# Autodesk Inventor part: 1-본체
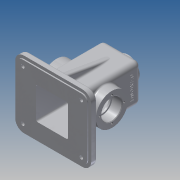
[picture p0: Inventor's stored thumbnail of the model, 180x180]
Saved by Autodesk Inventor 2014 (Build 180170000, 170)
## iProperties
Created: 2015-12
Part Number: 1-본체
Material: 알루미늄 6061
Document SubType Name: Modeling
Designer: Administrator
Mass: 888.312 g
Surface Area: 957.344 cm^2
Volume: 327.79 cm^3
Density: 2.71 g/cm^3
Appearance: 알루미늄 - 평지
Author: Administrator
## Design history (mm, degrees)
sketch "스케치1"
  geometry: L1 (-50, 57.5)-(50, 57.5); L2 (65, 42.5)-(65, -42.5); L3 (50, -57.5)-(-50, -57.5); L4 (-65, -42.5)-(-65, 42.5); L5 (-65, 57.5)-(65, -57.5); L6 (65, 57.5)-(-65, -57.5); A1 r 15 centre (50, -42.5) between (50, -57.5) and (65, -42.5); A2 r 15 centre (-50, -42.5) between (-65, -42.5) and (-50, -57.5); A3 r 15 centre (-50, 42.5) between (-50, 57.5) and (-65, 42.5); A4 r 15 centre (50, 42.5) between (65, 42.5) and (50, 57.5); 1 further point
  constraints: 12 end point, 8 point on circle, 8 point on line, 8 tangent, 4 centre point, 3 equal radius, 2 midpoint, 2 parallel, 1 horizontal, 1 perpendicular
  dimensions: "d0" = 130 distance of L5.end L6.end; "d1" = 115 distance of L6.start L5.end; "d4" = 15 radius of A1
extrude "돌출1" new body sketch "스케치1" distance "d2" = 10; taper "d3" = 0 deg
sketch "스케치2"
  geometry: L1 (-24.5, 32.5)-(24.5, 32.5); L2 (32.5, 24.5)-(32.5, -24.5); L3 (24.5, -32.5)-(-24.5, -32.5); L4 (-32.5, -24.5)-(-32.5, 24.5); L5 (-32.5, 32.5)-(32.5, -32.5); L6 (32.5, 32.5)-(-32.5, -32.5); A1 r 8 centre (-24.5, 24.5) between (-24.5, 32.5) and (-32.5, 24.5); A2 r 8 centre (24.5, 24.5) between (32.5, 24.5) and (24.5, 32.5); A3 r 8 centre (24.5, -24.5) between (24.5, -32.5) and (32.5, -24.5); A4 r 8 centre (-24.5, -24.5) between (-32.5, -24.5) and (-24.5, -32.5); 1 further point
  constraints: 12 end point, 8 point on circle, 8 point on line, 8 tangent, 4 centre point, 3 equal radius, 2 midpoint, 2 parallel, 1 horizontal, 1 perpendicular
  dimensions: "d5" = 65 distance of L5.end L6.end; "d6" = 65 distance of L6.start L5.end; "d7" = 8 radius of A1
extrude "돌출2" join sketch "스케치2" distance "d8" = 108; taper "d9" = 0 deg
sketch "스케치3"
  geometry: L1 (-65, -42.5)-(-65, 42.5) reference; L2 (50, -57.5)-(-50, -57.5) reference; L3 (65, 42.5)-(65, -42.5) reference; L4 (-50, 57.5)-(50, 57.5) reference; L5 (60, 42.5)-(60, -42.5); L6 (50, -52.5)-(-50, -52.5); L7 (-60, -42.5)-(-60, 42.5); L8 (-50, 52.5)-(50, 52.5); A1 r 15 centre (-50, -42.5) between (-65, -42.5) and (-50, -57.5) reference; A2 r 15 centre (50, -42.5) between (50, -57.5) and (65, -42.5) reference; A3 r 15 centre (50, 42.5) between (65, 42.5) and (50, 57.5) reference; A4 r 15 centre (-50, 42.5) between (-50, 57.5) and (-65, 42.5) reference; A5 r 10 centre (50, 42.5) between (60, 42.5) and (50, 52.5); A6 r 10 centre (50, -42.5) between (50, -52.5) and (60, -42.5); A7 r 10 centre (-50, -42.5) between (-60, -42.5) and (-50, -52.5); A8 r 10 centre (-50, 42.5) between (-50, 52.5) and (-60, 42.5); 1 further point
  constraints: 8 end point, 8 point on circle, 4 centre point, 7 other
  dimensions: "d10" = 5 distance between parallel lines of L4 L8
extrude "돌출3" join sketch "스케치3" distance "d11" = 2; taper "d12" = 0 deg
sketch "스케치4"
  geometry: L1 (-18, 0)-(67, 0) reference; L2 (67, -12)-(-18, -12) reference; C1 r 27.5 at (24.5, 43); 2 further points
  constraints: 1 centre point, 1 midpoint, 1 vertical alignment
  dimensions: "d13" = 55 diameter of C1; "d14" = 55 distance from line of L2 C1.centre
extrude "돌출4" join sketch "스케치4" distance "d15" = 15; taper "d16" = 0 deg
feature "쉘1" dims "d17" = 5
sketch "스케치5"
  geometry: L1 (22.5, -23)-(22.5, -72) reference; L2 (74.5, -20)-(25.5, -20) reference; L3 (77.5, -72)-(77.5, -23) reference; L4 (25.5, -75)-(74.5, -75) reference; L5 (105, -5)-(105, -90) reference; L6 (-5, -90)-(-5, -5) reference; L7 (100, -95)-(0, -95) reference; L8 (0, 0)-(100, 0) reference; L9 (22.5, -23)-(22.5, -72) reference; L10 (74.5, -20)-(25.5, -20) reference; L11 (77.5, -72)-(77.5, -23) reference; L12 (25.5, -75)-(74.5, -75) reference; L13 (105, -5)-(105, -90) reference; L14 (0, 0)-(100, 0) reference; L15 (-5, -90)-(-5, -5) reference; L16 (100, -95)-(0, -95) reference; A1 r 3 centre (25.5, -72) between (22.5, -72) and (25.5, -75) reference; A2 r 3 centre (25.5, -23) between (25.5, -20) and (22.5, -23) reference; A3 r 3 centre (74.5, -23) between (77.5, -23) and (74.5, -20) reference; A4 r 3 centre (74.5, -72) between (74.5, -75) and (77.5, -72) reference; A5 r 5 centre (100, -5) between (105, -5) and (100, 0) reference; A6 r 5 centre (0, -5) between (0, 0) and (-5, -5) reference; A7 r 5 centre (0, -90) between (-5, -90) and (0, -95) reference; A8 r 5 centre (100, -90) between (100, -95) and (105, -90) reference; A9 r 3 centre (25.5, -72) between (22.5, -72) and (25.5, -75) reference; A10 r 3 centre (25.5, -23) between (25.5, -20) and (22.5, -23) reference; A11 r 3 centre (74.5, -23) between (77.5, -23) and (74.5, -20) reference; A12 r 3 centre (74.5, -72) between (74.5, -75) and (77.5, -72) reference; A13 r 5 centre (100, -5) between (105, -5) and (100, 0) reference; A14 r 5 centre (0, -5) between (0, 0) and (-5, -5) reference; A15 r 5 centre (0, -90) between (-5, -90) and (0, -95) reference; A16 r 5 centre (100, -90) between (100, -95) and (105, -90) reference; 1 further point
extrude "돌출5" join sketch "스케치5" stored distance "d18" = 15; taper "d19" = 0 deg
sketch "스케치6"
  geometry: C1 r 20 at (0, 0); 1 further point
  constraints: 1 centre point, 1 coincident
  dimensions: "d20" = 40 diameter of C1
extrude "돌출6" join sketch "스케치6" distance "d21" = 10; taper "d22" = 0 deg
sketch "스케치11"
  geometry: C1 r 22.5 at (0, 0) reference; C2 r 27.5 at (0, 0) reference; 1 further point
extrude "돌출9" join sketch "스케치11" stored distance "d71" = 17; taper "d72" = 0 deg
sketch "스케치12"
  geometry: C1 r 27.5 at (0, 0) reference; C2 r 17.5 at (0, 0); 1 further point
  constraints: 1 centre point, 1 coincident
  dimensions: "d73" = 35 diameter of C2
extrude "돌출10" cut sketch "스케치12" distance "d74" = 17; taper "d75" = 0 deg
sketch "스케치13"
  geometry: C1 r 17.5 at (0, 0) reference; C2 r 15 at (0, 0); 1 further point
  constraints: 1 centre point, 1 coincident
  dimensions: "d76" = 30 diameter of C2
extrude "돌출11" cut sketch "스케치13" distance "d77" = 3; taper "d78" = 0 deg
sketch "스케치8"
  geometry: C1 r 20 at (0, 0) reference; C2 r 10.5 at (0, 0)
  constraints: 1 centre point, 1 coincident
  dimensions: "d44" = 21 diameter of C2
extrude "돌출7" cut sketch "스케치8" stored distance "d45" = 10; taper "d46" = 0 deg
sketch "스케치9"
  geometry: C1 r 10.5 at (0, 0) reference; 4 further points
  constraints: 1 vertical alignment, 5 other
  dimensions: "d47" = 14.5 distance of C1.centre point (0, 14.5); "d50" = 360 deg dimension on C1.centre point (0, 14.5) (derived)
hole "구멍3" sketch "스케치9" at (0, 14.5), (-14.5, 0), (0, -14.5), (14.5, 0) diameter "d52" = 2.459; stored, may be unused: countersink angle "d56" = 90 deg, drill point angle "d58" = 118 deg; dims "d53" = 7, "d54" = 4, "d55" = 2, "d57" = 9
sketch "스케치14"
  geometry: C1 r 17.5 at (0, 0) reference; 5 further points
  constraints: 1 vertical alignment, 5 other
  dimensions: "d79" = 21 distance of C1.centre point (0, 21); "d82" = 360 deg dimension on C1.centre point (0, 21) (derived)
hole "구멍5" sketch "스케치14" at (0, 21), (-21, 0), (0, -21), (21, 0) diameter "d84" = 3.242; stored, may be unused: countersink angle "d88" = 90 deg, drill point angle "d90" = 0 deg; dims "d85" = 8, "d86" = 4, "d87" = 2, "d89" = 10
sketch "스케치15"
  geometry: L1 (20, 128)-(20, 118) reference; L2 (20, 118)-(32.5, 118) reference; L3 (32.5, 118)-(32.5, 80.5) reference; L4 (32.5, 80.5)-(47.5, 80.5) reference; L5 (47.5, 80.5)-(47.5, 75.621) reference; L6 (47.5, 75.621)-(37.5, 75.621) reference; L7 (37.5, 75.621)-(37.5, 72.379) reference; L8 (37.5, 72.379)-(47.5, 72.379) reference; L9 (47.5, 72.379)-(47.5, 70.5) reference; L10 (47.5, 70.5)-(30.5, 70.5) reference; L11 (30.5, 70.5)-(30.5, 68) reference; L12 (30.5, 68)-(27.5, 68) reference; L13 (27.5, 68)-(27.5, 113) reference; L14 (27.5, 113)-(10.5, 113) reference; L15 (10.5, 113)-(10.5, 128) reference; L16 (10.5, 128)-(13.271, 128) reference; L17 (13.271, 128)-(13.271, 119) reference; L18 (13.271, 119)-(14.5, 118.261) reference; L19 (14.5, 118.261)-(15.73, 119) reference; L20 (15.73, 119)-(15.73, 128) reference; L21 (15.73, 128)-(20, 128) reference; L22 (-47.5, 80.5)-(-32.5, 80.5) reference; L23 (-32.5, 80.5)-(-32.5, 118) reference; L24 (-32.5, 118)-(-20, 118) reference; L25 (-20, 118)-(-20, 128) reference; L26 (-20, 128)-(-15.73, 128) reference; L27 (-15.73, 128)-(-15.73, 119) reference; L28 (-15.73, 119)-(-14.5, 118.261) reference; L29 (-14.5, 118.261)-(-13.271, 119) reference; L30 (-13.271, 119)-(-13.271, 128) reference; L31 (-13.271, 128)-(-10.5, 128) reference; L32 (-10.5, 128)-(-10.5, 113) reference; L33 (-10.5, 113)-(-27.5, 113) reference; L34 (-27.5, 113)-(-27.5, 68) reference; L35 (-27.5, 68)-(-30.5, 68) reference; L36 (-30.5, 68)-(-30.5, 70.5) reference; L37 (-30.5, 70.5)-(-47.5, 70.5) reference; L38 (-47.5, 70.5)-(-47.5, 72.379) reference; L39 (-47.5, 72.379)-(-37.5, 72.379) reference; L40 (-37.5, 72.379)-(-37.5, 75.621) reference; L41 (-37.5, 75.621)-(-47.5, 75.621) reference; L42 (-47.5, 75.621)-(-47.5, 80.5) reference; L43 (65, 10)-(65, 0) reference; L44 (65, 0)-(60, 0) reference; L45 (60, 0)-(60, -2) reference; L46 (60, -2)-(27.5, -2) reference; L47 (27.5, -2)-(27.5, 38) reference; L48 (27.5, 38)-(30.5, 38) reference; L49 (30.5, 38)-(30.5, 35.5) reference; L50 (30.5, 35.5)-(47.5, 35.5) reference; L51 (47.5, 35.5)-(47.5, 33.621) reference; L52 (47.5, 33.621)-(37.5, 33.621) reference; L53 (37.5, 33.621)-(37.5, 30.379) reference; L54 (37.5, 30.379)-(47.5, 30.379) reference; L55 (47.5, 30.379)-(47.5, 25.5) reference; L56 (47.5, 25.5)-(32.5, 25.5) reference; L57 (32.5, 25.5)-(32.5, 10) reference; L58 (32.5, 10)-(65, 10) reference; L59 (-65, 0)-(-65, 10) reference; L60 (-65, 10)-(-32.5, 10) reference; L61 (-32.5, 10)-(-32.5, 25.5) reference; L62 (-32.5, 25.5)-(-47.5, 25.5) reference; L63 (-47.5, 25.5)-(-47.5, 30.379) reference; L64 (-47.5, 30.379)-(-37.5, 30.379) reference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; 1 further point
  constraints: 4 end point, 2 midpoint, 2 point on line, 1 parallel, 1 perpendicular
  dimensions: "d91" = 15 distance between parallel lines of L47 L76; "d92" = 15 distance between parallel lines of L75 L71
extrude "돌출12" join sketch "스케치15" stored distance "d93" = 6; taper "d94" = 0 deg
sketch "스케치16"
  geometry: L1 (10, -57.5)-(0, -57.5) reference; L2 (0, -57.5)-(0, -52.5) reference; L3 (0, -52.5)-(-2, -52.5) reference; L4 (-2, -52.5)-(-2, -27.5) reference; L5 (-2, -27.5)-(113, -27.5) reference; L6 (113, -27.5)-(113, -10.5) reference; L7 (113, -10.5)-(128, -10.5) reference; L8 (128, -10.5)-(128, -13.271) reference; L9 (128, -13.271)-(119, -13.271) reference; L10 (119, -13.271)-(118.261, -14.5) reference; L11 (118.261, -14.5)-(119, -15.73) reference; L12 (119, -15.73)-(128, -15.73) reference; L13 (128, -15.73)-(128, -20) reference; L14 (128, -20)-(118, -20) reference; L15 (118, -20)-(118, -32.5) reference; L16 (118, -32.5)-(10, -32.5) reference; L17 (10, -32.5)-(10, -57.5) reference; L18 (0, 57.5)-(10, 57.5) reference; L19 (10, 57.5)-(10, 32.5) reference; L20 (10, 32.5)-(118, 32.5) reference; L21 (118, 32.5)-(118, 20) reference; L22 (118, 20)-(128, 20) reference; L23 (128, 20)-(128, 15.73) reference; L24 (128, 15.73)-(119, 15.73) reference; L25 (119, 15.73)-(118.261, 14.5) reference; L26 (118.261, 14.5)-(119, 13.271) reference; L27 (119, 13.271)-(128, 13.271) reference; L28 (128, 13.271)-(128, 10.5) reference; L29 (128, 10.5)-(113, 10.5) reference; L30 (113, 10.5)-(113, 27.5) reference; L31 (113, 27.5)-(-2, 27.5) reference; L32 (-2, 27.5)-(-2, 52.5) reference; L33 (-2, 52.5)-(0, 52.5) reference; L34 (0, 52.5)-(0, 57.5) reference; L35 (10, 47.5)-(95.069, 32.5); L36 (10, -47.5)-(95.069, -32.5); 1 further point
  constraints: 4 end point, 4 point on line
  dimensions: "d95" = 10 deg angle of L35 L18; "d96" = 10 deg angle of L1 L36; "d97" = 10 distance from line of L1 L36.start; "d98" = 10 distance from line of L18 L35.start
extrude "돌출13" join sketch "스케치16" stored distance "d99" = 10; taper "d100" = 0 deg
sketch "스케치17"
  geometry: C1 r 7.5 at (-50, 42.5); C2 r 7.5 at (50, 42.5); C3 r 7.5 at (50, -42.5); C4 r 7.5 at (-50, -42.5); A1 r 15 centre (-50, -42.5) between (-65, -42.5) and (-50, -57.5) reference; A2 r 15 centre (50, -42.5) between (50, -57.5) and (65, -42.5) reference; A3 r 15 centre (50, 42.5) between (65, 42.5) and (50, 57.5) reference; A4 r 15 centre (-50, 42.5) between (-50, 57.5) and (-65, 42.5) reference; 1 further point
  constraints: 4 centre point, 4 coincident
  dimensions: "d101" = 15 diameter of C1; "d102" = 15 diameter of C2; "d103" = 15 diameter of C3; "d104" = 15 diameter of C4
extrude "돌출14" join sketch "스케치17" distance "d105" = 1; taper "d106" = 0 deg
sketch "스케치18"
  geometry: L1 (7.5, 45.5)-(17.5, 45.5) reference; L2 (17.5, 45.5)-(17.5, 67) reference; L3 (25.5, 75)-(45, 75) reference; L4 (45, 75)-(45, 89.824) reference; L5 (45, 89.824)-(55, 89.824) reference; L6 (55, 89.824)-(55, 75) reference; L7 (55, 75)-(74.5, 75) reference; L8 (82.5, 67)-(82.5, 45.5) reference; L9 (82.5, 45.5)-(92.5, 45.5) reference; L10 (92.5, 45.5)-(92.5, 39.5) reference; L11 (92.5, 39.5)-(82.5, 39.5) reference; L12 (82.5, 39.5)-(82.5, 18) reference; L13 (74.5, 10)-(55, 10) reference; L14 (55, 10)-(55, -4.824) reference; L15 (55, -4.824)-(45, -4.824) reference; L16 (45, -4.824)-(45, 10) reference; L17 (45, 10)-(25.5, 10) reference; L18 (17.5, 18)-(17.5, 39.5) reference; L19 (17.5, 39.5)-(7.5, 39.5) reference; L20 (7.5, 39.5)-(7.5, 45.5) reference; L21 (22.5, 67)-(22.5, 18) reference; L22 (25.5, 15)-(74.5, 15) reference; L23 (77.5, 18)-(77.5, 67) reference; L24 (74.5, 70)-(25.5, 70) reference; C1 r 7.5 at (100, 0) reference; C2 r 7.5 at (0, 85) reference; C3 r 7.5 at (100, 85) reference; C4 r 7.5 at (0, 0) reference; C5 r 3 at (0, 85); C6 r 3 at (100, 85); C7 r 3 at (100, 0); C8 r 3 at (0, 0); A1 r 8 centre (25.5, 67) between (25.5, 75) and (17.5, 67) reference; A2 r 8 centre (74.5, 67) between (82.5, 67) and (74.5, 75) reference; A3 r 8 centre (74.5, 18) between (74.5, 10) and (82.5, 18) reference; A4 r 8 centre (25.5, 18) between (17.5, 18) and (25.5, 10) reference; A5 r 3 centre (25.5, 18) between (22.5, 18) and (25.5, 15) reference; A6 r 3 centre (74.5, 18) between (74.5, 15) and (77.5, 18) reference; A7 r 3 centre (74.5, 67) between (77.5, 67) and (74.5, 70) reference; A8 r 3 centre (25.5, 67) between (25.5, 70) and (22.5, 67) reference; 1 further point
  constraints: 4 centre point, 4 coincident
  dimensions: "d107" = 6 diameter of C5; "d108" = 6 diameter of C6; "d109" = 6 diameter of C7; "d110" = 6 diameter of C8
extrude "돌출15" cut sketch "스케치18" stored distance "d111" = 1; taper "d112" = 0 deg
fillet "모깎기1"
fillet "모깎기2"
fillet "모깎기3" dims "d113" = 3
fillet "모깎기4" dims "d114" = 3
fillet "모깎기5" dims "d115" = 3
fillet "모깎기6" dims "d116" = 3
fillet "모깎기7" dims "d117" = 3
fillet "모깎기8" dims "d118" = 8
chamfer "모따기1" distance "d119" = 1; stored, may be unused: second distance "d120" = 2, angle "d121" = 45 deg
chamfer "모따기2" distance "d122" = 1; stored, may be unused: second distance "d123" = 2, angle "d124" = 45 deg
chamfer "모따기3" distance "d125" = 1; stored, may be unused: second distance "d126" = 2, angle "d127" = 45 deg
fillet "모깎기9" dims "d128" = 0.3
fillet "모깎기10" dims "d129" = 3
fillet "모깎기11" dims "d130" = 3
fillet "모깎기12" dims "d131" = 3
fillet "모깎기13" dims "d132" = 3
sketch "스케치19"
  geometry: L1 (44.5, 18)-(4.5, 18) reference; 3 further points
  constraints: 1 midpoint, 1 vertical alignment, 1 other
  dimensions: "d133" = 26 distance from line of point (24.5, -8) L1
feature "엠보싱1" sketch "스케치19" dims "d5" = 65, "d6" = 65, "d7" = 8, "d134" = 0.5, "d135" = 0
node "솔리드1"
mirror "대칭2"
node "투영된 루프1"
node "투영된 루프2"
node "절단 모서리 투영1"
node "절단 모서리 투영2"
node "절단 모서리 투영3"
